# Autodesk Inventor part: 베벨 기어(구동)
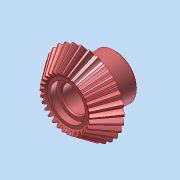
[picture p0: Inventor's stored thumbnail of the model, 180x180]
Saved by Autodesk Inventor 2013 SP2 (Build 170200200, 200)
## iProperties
Created: 2026-01
Part Number: 베벨 기어(구동)
Material: Generic
Document SubType Name: Modeling
Designer: a
Density: 1 g/cm^3
Author: a
변환 표준: STEP AP214IS
전처리기: Build: 200, Release: 2013 SP2 Update 6 - Date: Thu 07/17/2014
전송 단위: 밀리미터
불확실성: 0.01
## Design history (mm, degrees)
node "베벨 기어(구동)1"
body "Solid1"
node "기준1"
